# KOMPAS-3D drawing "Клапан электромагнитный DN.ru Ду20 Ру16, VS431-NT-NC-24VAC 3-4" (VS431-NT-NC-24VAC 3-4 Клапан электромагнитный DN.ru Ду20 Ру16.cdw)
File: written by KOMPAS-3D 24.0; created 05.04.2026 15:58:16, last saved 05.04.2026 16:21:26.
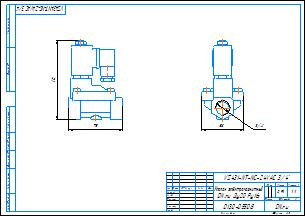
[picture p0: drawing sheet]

Document properties: c3d_UniqueCompID: ef56311e-7521-43dc-8291-0e6108b3d81d; Автор: artio; Класс точности: c; Знак неуказанной шероховатости: Шероховатость не задана; Рассекать на разрезах: Да; Автор: artio; Форматы листов документа: A3; Полное имя файла: VS431-NT-NC-24VAC 3-4 Клапан электромагнитный DN.ru Ду20 Ру16.m3d; Масса: 0.907; Наименование: Клапан электромагнитный DN.ru Ду20 Ру16; Количество листов документа: 1; Примечание: D130-05508

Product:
- Body: Тело 1  | qty 1
    Масса: 1.198355
- Part/product: Клапан электромагнитный DN.ru Ду20 Ру16  | designation VS431-NT-NC-24VAC 3-4
    Масса: 0.907
    Раздел спецификации: Прочие изделия
    Примечание: D130-05508
    additional columns: ef56311e-7521-43dc-8291-0e6108b3d81d; artio; c; Шероховатость не задана; Да

Views: Вид 1, Спереди, Проекционный вид 2
Referenced files in C:\Users\artio\OneDrive\Рабочий стол\Клапан электромагнитный DN.ru\VS431\VS431-ET-NC\: VS431-ET-NC-24VAC 3-4 Клапан электромагнитный DN.ru Ду20 Ру16.m3d
Referenced files in C:\Users\artio\OneDrive\Рабочий стол\Клапан электромагнитный DN.ru\VS431\VS431-NT-NC\: VS431-NT-NC-24VAC 3-4 Клапан электромагнитный DN.ru Ду20 Ру16.m3d, VS431-NT-NC-24VAC 3-4 Клапан электромагнитный DN.ru Ду20 Ру16.cdw
Referenced files in C:\Users\artio\OneDrive\Рабочий стол\Клапан электромагнитный DN.ru\VS431\VS431-NT-NC\VS431-NT-NC-24VAC\Ду20\: VS431-NT-NC-24VAC 3-4 Клапан электромагнитный DN.ru Ду20 Ру16.m3d
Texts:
  VS431-NT-NC-24VAC 3-4
  Клапан электромагнитный
  DN.ru Ду20 Ру16
  VS431-NT-NC-24VAC 3/4"
  VS431-NT-NC-24VAC 3/4"-
  Клапан электромагнитный DN.ru Ду20 Ру16
  VS431-NT-NC-24VAC 3-4 Клапан электромагнитный DN.ru Ду20 Ру16
Dimensions and other numbers on the sheet: 0; 3; 2; 4; 58; 3/4"; 75; 110; 1:1; 1; 0,91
